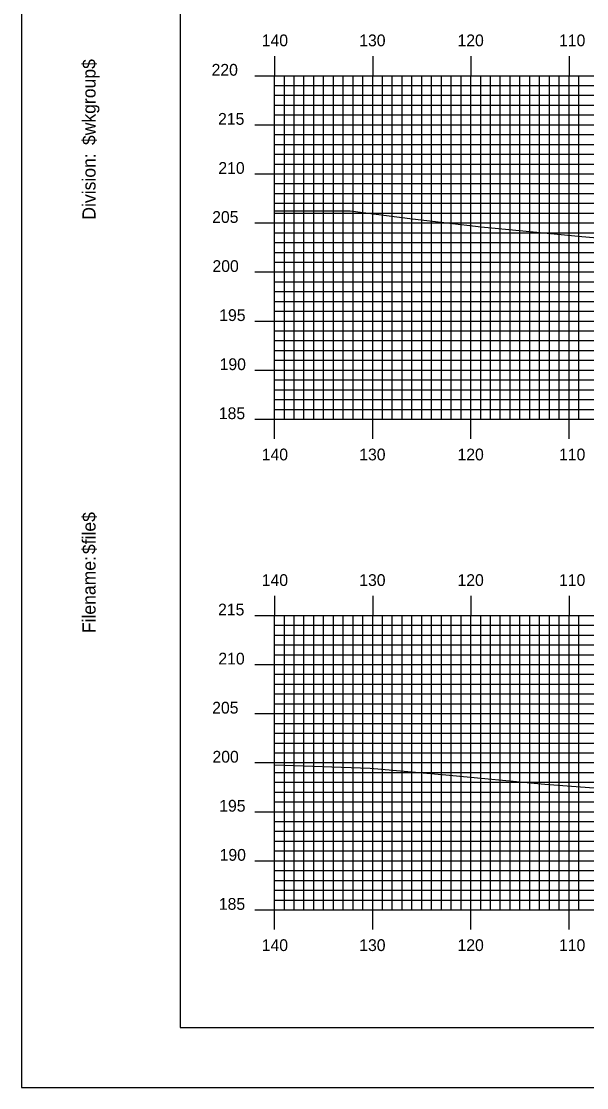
# Model space of a CAD drawing. Extents: x 1815702 to 1816046, y 442591 to 442811.
# Drawn here: x 1815702.3 to 1815759.8, y 442590.5 to 442699.2 of the extents above; entities that cross this region are included whole.
import ezdxf

# ---------------------------------------------------------------- set-up
doc = ezdxf.new("R2010")
doc.units = 0
for name, color, linetype in [('BORDER', 7, 'Continuous'), ('H_V ANNOTATION', 7, 'Continuous'), ('MAJOR', 7, 'Continuous'), ('MINOR', 7, 'Continuous'), ('PLOT BOUNDARY', 7, 'Continuous'), ('S_Roadway_Centerline', 7, 'Continuous')]:
    doc.layers.add(name, color=color, linetype=linetype)

msp = doc.modelspace()

# ---------------------------------------------------------------- linework, layer by layer
at = {"layer": 'BORDER'}
msp.add_lwpolyline([(1815718.45, 442596.67), (1816038.45, 442596.67), (1816038.45, 442806.67), (1815718.45, 442806.67)], close=True, dxfattribs=at)
at = {"layer": 'MAJOR'}
for p, q in [((1815728.05, 442695.67), (1815728.05, 442693.67)), ((1815738.05, 442695.67), (1815738.05, 442693.67)), ((1815748.05, 442695.67), (1815748.05, 442693.67)), ((1815758.05, 442695.67), (1815758.05, 442693.67)), ((1815726.04, 442693.67), (1815728.05, 442693.67)), ((1815728.05, 442693.67), (1816008.05, 442693.67)), ((1815728.05, 442658.67), (1815728.05, 442693.67)), ((1815728.05, 442658.67), (1815728.05, 442693.67)), ((1815728.05, 442693.67), (1816008.05, 442693.67)), ((1815738.05, 442658.67), (1815738.05, 442693.67)), ((1815748.05, 442658.67), (1815748.05, 442693.67)), ((1815758.05, 442658.67), (1815758.05, 442693.67)), ((1815726.04, 442688.67), (1815728.05, 442688.67)), ((1815728.05, 442688.67), (1816008.05, 442688.67)), ((1815726.04, 442683.67), (1815728.05, 442683.67)), ((1815728.05, 442683.67), (1816008.05, 442683.67)), ((1815726.04, 442678.67), (1815728.05, 442678.67)), ((1815728.05, 442678.67), (1816008.05, 442678.67)), ((1815726.04, 442673.67), (1815728.05, 442673.67)), ((1815728.05, 442673.67), (1816008.05, 442673.67)), ((1815726.04, 442668.67), (1815728.05, 442668.67)), ((1815728.05, 442668.67), (1816008.05, 442668.67)), ((1815726.04, 442663.67), (1815728.05, 442663.67)), ((1815728.05, 442663.67), (1816008.05, 442663.67)), ((1815726.04, 442658.67), (1815728.05, 442658.67)), ((1815728.05, 442658.67), (1816008.05, 442658.67)), ((1815728.05, 442658.67), (1816008.05, 442658.67)), ((1815728.05, 442656.66), (1815728.05, 442658.67)), ((1815738.05, 442656.66), (1815738.05, 442658.67)), ((1815748.05, 442656.66), (1815748.05, 442658.67)), ((1815758.05, 442656.66), (1815758.05, 442658.67)), ((1815728.05, 442640.67), (1815728.05, 442638.67)), ((1815738.05, 442640.67), (1815738.05, 442638.67)), ((1815748.05, 442640.67), (1815748.05, 442638.67)), ((1815758.05, 442640.67), (1815758.05, 442638.67)), ((1815726.04, 442638.67), (1815728.05, 442638.67)), ((1815728.05, 442638.67), (1816008.05, 442638.67)), ((1815728.05, 442608.67), (1815728.05, 442638.67)), ((1815728.05, 442608.67), (1815728.05, 442638.67)), ((1815728.05, 442638.67), (1816008.05, 442638.67)), ((1815738.05, 442608.67), (1815738.05, 442638.67)), ((1815748.05, 442608.67), (1815748.05, 442638.67)), ((1815758.05, 442608.67), (1815758.05, 442638.67)), ((1815726.04, 442633.67), (1815728.05, 442633.67)), ((1815728.05, 442633.67), (1816008.05, 442633.67)), ((1815726.04, 442628.67), (1815728.05, 442628.67)), ((1815728.05, 442628.67), (1816008.05, 442628.67)), ((1815726.04, 442623.67), (1815728.05, 442623.67)), ((1815728.05, 442623.67), (1816008.05, 442623.67)), ((1815726.04, 442618.67), (1815728.05, 442618.67)), ((1815728.05, 442618.67), (1816008.05, 442618.67)), ((1815726.04, 442613.67), (1815728.05, 442613.67)), ((1815728.05, 442613.67), (1816008.05, 442613.67)), ((1815726.04, 442608.67), (1815728.05, 442608.67)), ((1815728.05, 442608.67), (1816008.05, 442608.67)), ((1815728.05, 442608.67), (1816008.05, 442608.67)), ((1815728.05, 442606.66), (1815728.05, 442608.67)), ((1815738.05, 442606.66), (1815738.05, 442608.67)), ((1815748.05, 442606.66), (1815748.05, 442608.67)), ((1815758.05, 442606.66), (1815758.05, 442608.67))]:
    msp.add_line(p, q, dxfattribs=at)
at = {"layer": 'MINOR'}
for p, q in [((1815729.05, 442658.67), (1815729.05, 442693.67)), ((1815730.05, 442658.67), (1815730.05, 442693.67)), ((1815731.05, 442658.67), (1815731.05, 442693.67)), ((1815732.05, 442658.67), (1815732.05, 442693.67)), ((1815733.05, 442658.67), (1815733.05, 442693.67)), ((1815734.05, 442658.67), (1815734.05, 442693.67)), ((1815735.05, 442658.67), (1815735.05, 442693.67)), ((1815736.05, 442658.67), (1815736.05, 442693.67)), ((1815737.05, 442658.67), (1815737.05, 442693.67)), ((1815739.05, 442658.67), (1815739.05, 442693.67)), ((1815740.05, 442658.67), (1815740.05, 442693.67)), ((1815741.05, 442658.67), (1815741.05, 442693.67)), ((1815742.05, 442658.67), (1815742.05, 442693.67)), ((1815743.05, 442658.67), (1815743.05, 442693.67)), ((1815744.05, 442658.67), (1815744.05, 442693.67)), ((1815745.05, 442658.67), (1815745.05, 442693.67)), ((1815746.05, 442658.67), (1815746.05, 442693.67)), ((1815747.05, 442658.67), (1815747.05, 442693.67)), ((1815749.05, 442658.67), (1815749.05, 442693.67)), ((1815750.05, 442658.67), (1815750.05, 442693.67)), ((1815751.05, 442658.67), (1815751.05, 442693.67)), ((1815752.05, 442658.67), (1815752.05, 442693.67)), ((1815753.05, 442658.67), (1815753.05, 442693.67)), ((1815754.05, 442658.67), (1815754.05, 442693.67)), ((1815755.05, 442658.67), (1815755.05, 442693.67)), ((1815756.05, 442658.67), (1815756.05, 442693.67)), ((1815757.05, 442658.67), (1815757.05, 442693.67)), ((1815759.05, 442658.67), (1815759.05, 442693.67)), ((1815728.05, 442692.67), (1816008.05, 442692.67)), ((1815728.05, 442692.67), (1815730.05, 442692.67)), ((1815728.05, 442691.67), (1816008.05, 442691.67)), ((1815728.05, 442691.67), (1815730.05, 442691.67)), ((1815728.05, 442690.67), (1816008.05, 442690.67)), ((1815728.05, 442690.67), (1815730.05, 442690.67)), ((1815728.05, 442689.67), (1816008.05, 442689.67)), ((1815728.05, 442689.67), (1815730.05, 442689.67)), ((1815728.05, 442687.67), (1816008.05, 442687.67)), ((1815728.05, 442687.67), (1815730.05, 442687.67)), ((1815728.05, 442686.67), (1816008.05, 442686.67)), ((1815728.05, 442686.67), (1815730.05, 442686.67)), ((1815728.05, 442685.67), (1816008.05, 442685.67)), ((1815728.05, 442685.67), (1815730.05, 442685.67)), ((1815728.05, 442684.67), (1816008.05, 442684.67)), ((1815728.05, 442684.67), (1815730.05, 442684.67)), ((1815728.05, 442682.67), (1816008.05, 442682.67)), ((1815728.05, 442682.67), (1815730.05, 442682.67)), ((1815728.05, 442681.67), (1816008.05, 442681.67)), ((1815728.05, 442681.67), (1815730.05, 442681.67)), ((1815728.05, 442680.67), (1816008.05, 442680.67)), ((1815728.05, 442680.67), (1815730.05, 442680.67)), ((1815728.05, 442679.67), (1816008.05, 442679.67)), ((1815728.05, 442679.67), (1815730.05, 442679.67)), ((1815728.05, 442677.67), (1816008.05, 442677.67)), ((1815728.05, 442677.67), (1815730.05, 442677.67)), ((1815728.05, 442676.67), (1816008.05, 442676.67)), ((1815728.05, 442676.67), (1815730.05, 442676.67)), ((1815728.05, 442675.67), (1816008.05, 442675.67)), ((1815728.05, 442675.67), (1815730.05, 442675.67)), ((1815728.05, 442674.67), (1816008.05, 442674.67)), ((1815728.05, 442674.67), (1815730.05, 442674.67)), ((1815728.05, 442672.67), (1816008.05, 442672.67)), ((1815728.05, 442672.67), (1815730.05, 442672.67)), ((1815728.05, 442671.67), (1816008.05, 442671.67)), ((1815728.05, 442671.67), (1815730.05, 442671.67)), ((1815728.05, 442670.67), (1816008.05, 442670.67)), ((1815728.05, 442670.67), (1815730.05, 442670.67)), ((1815728.05, 442669.67), (1816008.05, 442669.67)), ((1815728.05, 442669.67), (1815730.05, 442669.67)), ((1815728.05, 442667.67), (1816008.05, 442667.67)), ((1815728.05, 442667.67), (1815730.05, 442667.67)), ((1815728.05, 442666.67), (1816008.05, 442666.67)), ((1815728.05, 442666.67), (1815730.05, 442666.67)), ((1815728.05, 442665.67), (1816008.05, 442665.67)), ((1815728.05, 442665.67), (1815730.05, 442665.67)), ((1815728.05, 442664.67), (1816008.05, 442664.67)), ((1815728.05, 442664.67), (1815730.05, 442664.67)), ((1815728.05, 442662.67), (1816008.05, 442662.67)), ((1815728.05, 442662.67), (1815730.05, 442662.67)), ((1815728.05, 442661.67), (1816008.05, 442661.67)), ((1815728.05, 442661.67), (1815730.05, 442661.67)), ((1815728.05, 442660.67), (1816008.05, 442660.67)), ((1815728.05, 442660.67), (1815730.05, 442660.67)), ((1815728.05, 442659.67), (1816008.05, 442659.67)), ((1815728.05, 442659.67), (1815730.05, 442659.67)), ((1815729.05, 442608.67), (1815729.05, 442638.67)), ((1815730.05, 442608.67), (1815730.05, 442638.67)), ((1815731.05, 442608.67), (1815731.05, 442638.67)), ((1815732.05, 442608.67), (1815732.05, 442638.67)), ((1815733.05, 442608.67), (1815733.05, 442638.67)), ((1815734.05, 442608.67), (1815734.05, 442638.67)), ((1815735.05, 442608.67), (1815735.05, 442638.67)), ((1815736.05, 442608.67), (1815736.05, 442638.67)), ((1815737.05, 442608.67), (1815737.05, 442638.67)), ((1815739.05, 442608.67), (1815739.05, 442638.67)), ((1815740.05, 442608.67), (1815740.05, 442638.67)), ((1815741.05, 442608.67), (1815741.05, 442638.67)), ((1815742.05, 442608.67), (1815742.05, 442638.67)), ((1815743.05, 442608.67), (1815743.05, 442638.67)), ((1815744.05, 442608.67), (1815744.05, 442638.67)), ((1815745.05, 442608.67), (1815745.05, 442638.67)), ((1815746.05, 442608.67), (1815746.05, 442638.67)), ((1815747.05, 442608.67), (1815747.05, 442638.67)), ((1815749.05, 442608.67), (1815749.05, 442638.67)), ((1815750.05, 442608.67), (1815750.05, 442638.67)), ((1815751.05, 442608.67), (1815751.05, 442638.67)), ((1815752.05, 442608.67), (1815752.05, 442638.67)), ((1815753.05, 442608.67), (1815753.05, 442638.67)), ((1815754.05, 442608.67), (1815754.05, 442638.67)), ((1815755.05, 442608.67), (1815755.05, 442638.67)), ((1815756.05, 442608.67), (1815756.05, 442638.67)), ((1815757.05, 442608.67), (1815757.05, 442638.67)), ((1815759.05, 442608.67), (1815759.05, 442638.67)), ((1815728.05, 442637.67), (1816008.05, 442637.67)), ((1815728.05, 442637.67), (1815730.05, 442637.67)), ((1815728.05, 442636.67), (1816008.05, 442636.67)), ((1815728.05, 442636.67), (1815730.05, 442636.67)), ((1815728.05, 442635.67), (1816008.05, 442635.67)), ((1815728.05, 442635.67), (1815730.05, 442635.67)), ((1815728.05, 442634.67), (1816008.05, 442634.67)), ((1815728.05, 442634.67), (1815730.05, 442634.67)), ((1815728.05, 442632.67), (1816008.05, 442632.67)), ((1815728.05, 442632.67), (1815730.05, 442632.67)), ((1815728.05, 442631.67), (1816008.05, 442631.67)), ((1815728.05, 442631.67), (1815730.05, 442631.67)), ((1815728.05, 442630.67), (1816008.05, 442630.67)), ((1815728.05, 442630.67), (1815730.05, 442630.67)), ((1815728.05, 442629.67), (1816008.05, 442629.67)), ((1815728.05, 442629.67), (1815730.05, 442629.67)), ((1815728.05, 442627.67), (1816008.05, 442627.67)), ((1815728.05, 442627.67), (1815730.05, 442627.67)), ((1815728.05, 442626.67), (1816008.05, 442626.67)), ((1815728.05, 442626.67), (1815730.05, 442626.67)), ((1815728.05, 442625.67), (1816008.05, 442625.67)), ((1815728.05, 442625.67), (1815730.05, 442625.67)), ((1815728.05, 442624.67), (1816008.05, 442624.67)), ((1815728.05, 442624.67), (1815730.05, 442624.67)), ((1815728.05, 442622.67), (1816008.05, 442622.67)), ((1815728.05, 442622.67), (1815730.05, 442622.67)), ((1815728.05, 442621.67), (1816008.05, 442621.67)), ((1815728.05, 442621.67), (1815730.05, 442621.67)), ((1815728.05, 442620.67), (1816008.05, 442620.67)), ((1815728.05, 442620.67), (1815730.05, 442620.67)), ((1815728.05, 442619.67), (1816008.05, 442619.67)), ((1815728.05, 442619.67), (1815730.05, 442619.67)), ((1815728.05, 442617.67), (1816008.05, 442617.67)), ((1815728.05, 442617.67), (1815730.05, 442617.67)), ((1815728.05, 442616.67), (1816008.05, 442616.67)), ((1815728.05, 442616.67), (1815730.05, 442616.67)), ((1815728.05, 442615.67), (1816008.05, 442615.67)), ((1815728.05, 442615.67), (1815730.05, 442615.67)), ((1815728.05, 442614.67), (1816008.05, 442614.67)), ((1815728.05, 442614.67), (1815730.05, 442614.67)), ((1815728.05, 442612.67), (1816008.05, 442612.67)), ((1815728.05, 442612.67), (1815730.05, 442612.67)), ((1815728.05, 442611.67), (1816008.05, 442611.67)), ((1815728.05, 442611.67), (1815730.05, 442611.67)), ((1815728.05, 442610.67), (1816008.05, 442610.67)), ((1815728.05, 442610.67), (1815730.05, 442610.67)), ((1815728.05, 442609.67), (1816008.05, 442609.67)), ((1815728.05, 442609.67), (1815730.05, 442609.67))]:
    msp.add_line(p, q, dxfattribs=at)
at = {"layer": 'PLOT BOUNDARY'}
msp.add_lwpolyline([(1815702.26, 442590.55), (1816042.26, 442590.55), (1816042.26, 442810.55), (1815702.26, 442810.55)], close=True, dxfattribs=at)
at = {"layer": 'S_Roadway_Centerline'}
for points in [[(1815728.05, 442679.91), (1815735.76, 442679.89), (1815742.1, 442679.09), (1815749.09, 442678.28), (1815759.36, 442677.27), (1815762.9, 442676.99), (1815774.19, 442675.96), (1815776.58, 442675.75), (1815777.48, 442675.7), (1815792.64, 442674.27), (1815802.89, 442673.25), (1815809.56, 442672.51), (1815823.05, 442671.65)], [(1815728.05, 442623.44), (1815737.79, 442623.1), (1815745.5, 442622.41), (1815755.6, 442621.47), (1815760.14, 442621.14), (1815771.69, 442620.83), (1815781.23, 442620.56), (1815789.2, 442620.17), (1815799.6, 442619.67), (1815805.51, 442619.47), (1815817.11, 442619.1)]]:
    msp.add_lwpolyline(points, dxfattribs=at)

# ---------------------------------------------------------------- texts
at = {"layer": 'BORDER'}
for s, p in [('$wkgroup$', (1815709.82, 442686.6)), ('Division:', (1815709.82, 442679)), ('$file$', (1815709.82, 442644.92)), ('Filename:', (1815709.82, 442636.86))]:
    msp.add_text(s, height=1.339, rotation=90, dxfattribs=at).set_placement(p)
at = {"layer": 'H_V ANNOTATION'}
for s, p in [('140', (1815726.75, 442696.67)), ('130', (1815736.68, 442696.67)), ('120', (1815746.69, 442696.67)), ('110', (1815757.03, 442696.67)), ('220', (1815721.64, 442693.67)), ('215', (1815722.3, 442688.67)), ('210', (1815722.33, 442683.67)), ('205', (1815721.7, 442678.67)), ('200', (1815721.73, 442673.67)), ('195', (1815722.42, 442668.67)), ('190', (1815722.46, 442663.67)), ('185', (1815722.38, 442658.67)), ('140', (1815726.75, 442654.47)), ('130', (1815736.68, 442654.47)), ('120', (1815746.69, 442654.47)), ('110', (1815757.03, 442654.47)), ('140', (1815726.75, 442641.67)), ('130', (1815736.68, 442641.67)), ('120', (1815746.69, 442641.67)), ('110', (1815757.03, 442641.67)), ('215', (1815722.3, 442638.67)), ('210', (1815722.33, 442633.67)), ('205', (1815721.7, 442628.67)), ('200', (1815721.73, 442623.67)), ('195', (1815722.42, 442618.67)), ('190', (1815722.46, 442613.67)), ('185', (1815722.38, 442608.67)), ('140', (1815726.75, 442604.47)), ('130', (1815736.68, 442604.47)), ('120', (1815746.69, 442604.47)), ('110', (1815757.03, 442604.47))]:
    msp.add_text(s, height=1.2, dxfattribs=at).set_placement(p)
at = {"layer": 'MAJOR'}
for p in [(1815728.04, 442658.67), (1815728.04, 442608.67)]:
    msp.add_text('-', height=0.012, dxfattribs=at).set_placement(p)

doc.saveas('drawing.dxf')
